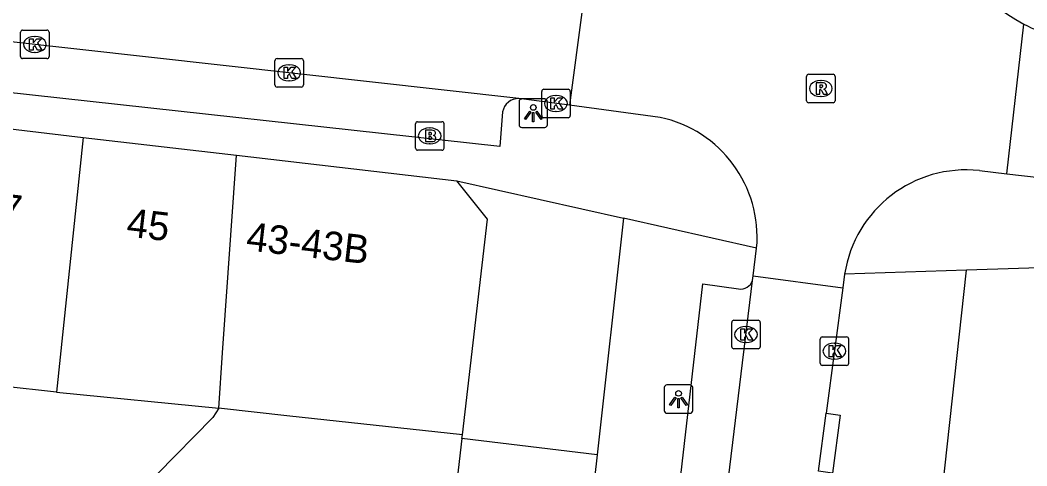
# Model space of a CAD drawing. Extents: x 161696 to 162377, y 380761 to 381673.
# Drawn here: x 162000.63 to 162035.97, y 381141.72 to 381157.36 of the extents above; entities that cross this region are included whole.
import ezdxf

# ---------------------------------------------------------------- set-up
doc = ezdxf.new("R2010")
doc.units = 0
for name, color, linetype in [('IMGEO_Brandkraan', 7, 'Continuous'), ('IMGEO_Kolk', 7, 'Continuous'), ('IMGEO_Lichtpunt', 7, 'Continuous'), ('IMGEO_Pand', 7, 'Continuous'), ('IMGEO_Pand_nummerreeks', 7, 'Continuous'), ('IMGEO_Rijbaan_lokaal_open', 7, 'Continuous'), ('IMGEO_Rioolput', 7, 'Continuous'), ('IMGEO_Voetpad_open', 7, 'Continuous')]:
    doc.layers.add(name, color=color, linetype=linetype)

msp = doc.modelspace()

# ---------------------------------------------------------------- linework, layer by layer
at = {"layer": 'IMGEO_Brandkraan'}
for p, q in [((162014.51, 381152.872), (162014.51, 381153.724)), ((162014.585, 381153.798), (162015.437, 381153.798)), ((162015.511, 381153.724), (162015.511, 381152.872)), ((162014.998, 381153.578), (162015.023, 381153.578)), ((162015.021, 381153.018), (162014.996, 381153.018)), ((162015.437, 381152.798), (162014.585, 381152.798))]:
    msp.add_line(p, q, dxfattribs=at)
for points in [[(162014.51, 381152.872), (162014.51, 381153.724)], [(162014.585, 381153.798), (162015.437, 381153.798)], [(162015.511, 381153.724), (162015.511, 381152.872)], [(162014.858, 381153.498), (162014.858, 381153.098), (162015.071, 381153.098)], [(162015.089, 381153.498), (162014.858, 381153.498)], [(162015.037, 381153.417), (162014.983, 381153.417), (162014.983, 381153.341)], [(162014.983, 381153.341), (162015.036, 381153.341)], [(162015.045, 381153.265), (162014.983, 381153.265), (162014.983, 381153.184)], [(162014.983, 381153.184), (162015.045, 381153.184)], [(162015.437, 381152.798), (162014.585, 381152.798)]]:
    msp.add_lwpolyline(points, dxfattribs=at)
for centre, radius, start, end in [((162014.587, 381153.722), 0.0765, 91.552, 178.448), ((162014.587, 381153.722), 0.0765, 91.552, 178.448), ((162015.435, 381153.722), 0.0765, 1.552, 88.448), ((162015.435, 381153.722), 0.0765, 1.552, 88.448), ((162015.038, 381153.379), 0.0379, 267.8285, 90.9355), ((162015.093, 381153.353), 0.145, 59.4692, 91.5367), ((162015.118, 381153.4), 0.0922, 285.5137, 58.1501), ((162015.123, 381153.208), 0.105, 301.3115, 78.989), ((162015.046, 381153.224), 0.0404, 269.8759, 90.5077), ((162015.077, 381153.349), 0.251, 268.6676, 293.5347), ((162014.587, 381152.874), 0.0765, 181.552, 268.448), ((162014.587, 381152.874), 0.0765, 181.552, 268.448), ((162015.435, 381152.874), 0.0765, 271.552, 358.448), ((162015.435, 381152.874), 0.0765, 271.552, 358.448)]:
    msp.add_arc(centre, radius, start, end, dxfattribs=at)
for centre, major_axis, ratio, start_param, end_param in [((162014.997, 381153.298), (-0.387, 0.002), 0.722429, 4.712389, 7.853982), ((162015.022, 381153.298), (-0.39, 0.002), 0.717154, 1.570796, 4.712389)]:
    msp.add_ellipse(centre, major_axis=major_axis, ratio=ratio, start_param=start_param, end_param=end_param, dxfattribs=at)
at = {"layer": 'IMGEO_Kolk'}
for p, q in [((162000.646, 381156.086), (162000.646, 381156.938)), ((162000.721, 381157.012), (162001.573, 381157.012)), ((162001.647, 381156.938), (162001.647, 381156.086)), ((162001.134, 381156.792), (162001.159, 381156.792)), ((162001.157, 381156.232), (162001.132, 381156.232)), ((162001.573, 381156.012), (162000.721, 381156.012)), ((162009.575, 381155.087), (162009.575, 381155.939)), ((162009.65, 381156.013), (162010.502, 381156.013)), ((162010.063, 381155.793), (162010.088, 381155.793)), ((162010.576, 381155.939), (162010.576, 381155.087)), ((162010.086, 381155.233), (162010.061, 381155.233)), ((162010.502, 381155.013), (162009.65, 381155.013)), ((162018.94, 381154.011), (162018.94, 381154.863)), ((162019.015, 381154.937), (162019.867, 381154.937)), ((162019.428, 381154.717), (162019.453, 381154.717)), ((162019.941, 381154.863), (162019.941, 381154.011)), ((162019.451, 381154.157), (162019.426, 381154.157)), ((162019.867, 381153.937), (162019.015, 381153.937)), ((162025.612, 381145.9), (162025.612, 381146.752)), ((162025.687, 381146.826), (162026.539, 381146.826)), ((162026.1, 381146.606), (162026.125, 381146.606)), ((162026.613, 381146.752), (162026.613, 381145.9)), ((162028.789, 381146.242), (162029.641, 381146.242)), ((162026.123, 381146.046), (162026.098, 381146.046)), ((162028.714, 381145.316), (162028.714, 381146.168)), ((162029.202, 381146.022), (162029.227, 381146.022)), ((162029.715, 381146.168), (162029.715, 381145.316)), ((162026.539, 381145.826), (162025.687, 381145.826)), ((162029.641, 381145.242), (162028.789, 381145.242)), ((162029.225, 381145.462), (162029.2, 381145.462))]:
    msp.add_line(p, q, dxfattribs=at)
for points in [[(162000.646, 381156.086), (162000.646, 381156.938)], [(162000.721, 381157.012), (162001.573, 381157.012)], [(162001.647, 381156.938), (162001.647, 381156.086)], [(162000.967, 381156.712), (162001.09, 381156.712), (162001.09, 381156.561), (162001.22, 381156.712), (162001.384, 381156.712), (162001.238, 381156.561), (162001.391, 381156.312), (162001.239, 381156.312), (162001.154, 381156.476), (162001.09, 381156.409), (162001.09, 381156.312), (162000.967, 381156.312), (162000.967, 381156.712)], [(162001.573, 381156.012), (162000.721, 381156.012)], [(162009.575, 381155.087), (162009.575, 381155.939)], [(162009.65, 381156.013), (162010.502, 381156.013)], [(162010.576, 381155.939), (162010.576, 381155.087)], [(162009.896, 381155.713), (162010.019, 381155.713), (162010.019, 381155.562), (162010.149, 381155.713), (162010.313, 381155.713), (162010.167, 381155.562), (162010.32, 381155.313), (162010.168, 381155.313), (162010.083, 381155.477), (162010.019, 381155.41), (162010.019, 381155.313), (162009.896, 381155.313), (162009.896, 381155.713)], [(162010.502, 381155.013), (162009.65, 381155.013)], [(162018.94, 381154.011), (162018.94, 381154.863)], [(162019.015, 381154.937), (162019.867, 381154.937)], [(162019.941, 381154.863), (162019.941, 381154.011)], [(162019.261, 381154.637), (162019.384, 381154.637), (162019.384, 381154.486), (162019.514, 381154.637), (162019.678, 381154.637), (162019.532, 381154.486), (162019.685, 381154.237), (162019.533, 381154.237), (162019.448, 381154.401), (162019.384, 381154.334), (162019.384, 381154.237), (162019.261, 381154.237), (162019.261, 381154.637)], [(162019.867, 381153.937), (162019.015, 381153.937)], [(162025.612, 381145.9), (162025.612, 381146.752)], [(162025.687, 381146.826), (162026.539, 381146.826)], [(162026.613, 381146.752), (162026.613, 381145.9)], [(162025.933, 381146.526), (162026.056, 381146.526), (162026.056, 381146.375), (162026.186, 381146.526), (162026.35, 381146.526), (162026.204, 381146.375), (162026.357, 381146.126), (162026.205, 381146.126), (162026.12, 381146.29), (162026.056, 381146.223), (162026.056, 381146.126), (162025.933, 381146.126), (162025.933, 381146.526)], [(162028.789, 381146.242), (162029.641, 381146.242)], [(162028.714, 381145.316), (162028.714, 381146.168)], [(162029.035, 381145.942), (162029.158, 381145.942), (162029.158, 381145.791), (162029.288, 381145.942), (162029.452, 381145.942), (162029.306, 381145.791), (162029.459, 381145.542), (162029.307, 381145.542), (162029.222, 381145.706), (162029.158, 381145.639), (162029.158, 381145.542), (162029.035, 381145.542), (162029.035, 381145.942)], [(162029.715, 381146.168), (162029.715, 381145.316)], [(162026.539, 381145.826), (162025.687, 381145.826)], [(162029.641, 381145.242), (162028.789, 381145.242)]]:
    msp.add_lwpolyline(points, dxfattribs=at)
for centre, start, end in [((162000.723, 381156.936), 91.552, 178.448), ((162000.723, 381156.936), 91.552, 178.448), ((162001.571, 381156.936), 1.552, 88.448), ((162001.571, 381156.936), 1.552, 88.448), ((162000.723, 381156.088), 181.552, 268.448), ((162000.723, 381156.088), 181.552, 268.448), ((162001.571, 381156.088), 271.552, 358.448), ((162001.571, 381156.088), 271.552, 358.448), ((162009.652, 381155.937), 91.552, 178.448), ((162009.652, 381155.937), 91.552, 178.448), ((162010.5, 381155.937), 1.552, 88.448), ((162010.5, 381155.937), 1.552, 88.448), ((162009.652, 381155.089), 181.552, 268.448), ((162009.652, 381155.089), 181.552, 268.448), ((162010.5, 381155.089), 271.552, 358.448), ((162010.5, 381155.089), 271.552, 358.448), ((162019.017, 381154.861), 91.552, 178.448), ((162019.017, 381154.861), 91.552, 178.448), ((162019.865, 381154.861), 1.552, 88.448), ((162019.865, 381154.861), 1.552, 88.448), ((162019.017, 381154.013), 181.552, 268.448), ((162019.017, 381154.013), 181.552, 268.448), ((162019.865, 381154.013), 271.552, 358.448), ((162019.865, 381154.013), 271.552, 358.448), ((162025.689, 381146.75), 91.552, 178.448), ((162025.689, 381146.75), 91.552, 178.448), ((162026.537, 381146.75), 1.552, 88.448), ((162026.537, 381146.75), 1.552, 88.448), ((162028.791, 381146.166), 91.552, 178.448), ((162028.791, 381146.166), 91.552, 178.448), ((162029.639, 381146.166), 1.552, 88.448), ((162029.639, 381146.166), 1.552, 88.448), ((162025.689, 381145.902), 181.552, 268.448), ((162025.689, 381145.902), 181.552, 268.448), ((162026.537, 381145.902), 271.552, 358.448), ((162026.537, 381145.902), 271.552, 358.448), ((162028.791, 381145.318), 181.552, 268.448), ((162028.791, 381145.318), 181.552, 268.448), ((162029.639, 381145.318), 271.552, 358.448), ((162029.639, 381145.318), 271.552, 358.448)]:
    msp.add_arc(centre, 0.0765, start, end, dxfattribs=at)
for centre, major_axis, ratio, start_param, end_param in [((162001.133, 381156.512), (-0.387, 0.002), 0.722429, 4.712389, 7.853982), ((162001.158, 381156.512), (-0.39, 0.002), 0.717154, 1.570796, 4.712389), ((162010.062, 381155.513), (-0.387, 0.002), 0.722429, 4.712389, 7.853982), ((162010.087, 381155.513), (-0.39, 0.002), 0.717154, 1.570796, 4.712389), ((162019.427, 381154.437), (-0.387, 0.002), 0.722429, 4.712389, 7.853982), ((162019.452, 381154.437), (-0.39, 0.002), 0.717154, 1.570796, 4.712389), ((162026.099, 381146.326), (-0.387, 0.002), 0.722429, 4.712389, 7.853982), ((162026.124, 381146.326), (-0.39, 0.002), 0.717154, 1.570796, 4.712389), ((162029.201, 381145.742), (-0.387, 0.002), 0.722429, 4.712389, 7.853982), ((162029.226, 381145.742), (-0.39, 0.002), 0.717154, 1.570796, 4.712389)]:
    msp.add_ellipse(centre, major_axis=major_axis, ratio=ratio, start_param=start_param, end_param=end_param, dxfattribs=at)
at = {"layer": 'IMGEO_Lichtpunt'}
for p, q in [((162018.146, 381154.5), (162018.146, 381153.693)), ((162018.146, 381154.5), (162018.146, 381153.693)), ((162019.048, 381154.595), (162018.24, 381154.595)), ((162019.048, 381154.595), (162018.24, 381154.595)), ((162019.142, 381153.693), (162019.142, 381154.5)), ((162019.142, 381153.693), (162019.142, 381154.5)), ((162018.24, 381153.599), (162019.048, 381153.599)), ((162018.24, 381153.599), (162019.048, 381153.599)), ((162023.244, 381144.463), (162023.244, 381143.656)), ((162023.244, 381144.463), (162023.244, 381143.656)), ((162024.146, 381144.558), (162023.338, 381144.558)), ((162024.146, 381144.558), (162023.338, 381144.558)), ((162024.24, 381143.656), (162024.24, 381144.463)), ((162024.24, 381143.656), (162024.24, 381144.463)), ((162023.338, 381143.562), (162024.146, 381143.562)), ((162023.338, 381143.562), (162024.146, 381143.562))]:
    msp.add_line(p, q, dxfattribs=at)
for points in [[(162018.52, 381154.164), (162018.559, 381154.136), (162018.371, 381153.874), (162018.333, 381153.901), (162018.52, 381154.164)], [(162018.622, 381154.116), (162018.669, 381154.116), (162018.669, 381153.794), (162018.622, 381153.794), (162018.622, 381154.116)], [(162018.732, 381154.136), (162018.77, 381154.163), (162018.957, 381153.901), (162018.918, 381153.873), (162018.732, 381154.136)], [(162023.618, 381144.127), (162023.657, 381144.099), (162023.469, 381143.837), (162023.431, 381143.864), (162023.618, 381144.127)], [(162023.83, 381144.099), (162023.868, 381144.126), (162024.055, 381143.864), (162024.016, 381143.836), (162023.83, 381144.099)], [(162023.72, 381144.079), (162023.767, 381144.079), (162023.767, 381143.757), (162023.72, 381143.757), (162023.72, 381144.079)]]:
    msp.add_lwpolyline(points, dxfattribs=at)
for centre in [(162018.645, 381154.298), (162023.743, 381144.261)]:
    msp.add_circle(centre, 0.0994, dxfattribs=at)
for centre, start, end in [((162018.24, 381154.5), 90, 180), ((162018.24, 381154.5), 90, 180), ((162019.048, 381154.5), 0, 90), ((162019.048, 381154.5), 0, 90), ((162018.24, 381153.693), 180, 270), ((162018.24, 381153.693), 180, 270), ((162019.048, 381153.693), 270, 0), ((162019.048, 381153.693), 270, 360), ((162023.338, 381144.463), 90, 180), ((162023.338, 381144.463), 90, 180), ((162024.146, 381144.463), 0, 90), ((162024.146, 381144.463), 0, 90), ((162023.338, 381143.656), 180, 270), ((162023.338, 381143.656), 180, 270), ((162024.146, 381143.656), 270, 0), ((162024.146, 381143.656), 270, 360)]:
    msp.add_arc(centre, 0.0946, start, end, dxfattribs=at)
at = {"layer": 'IMGEO_Pand'}
for points in [[(161997.875, 381153.822), (161999.999, 381153.577), (162002.848, 381153.247)], [(162002.848, 381153.247), (162001.908, 381144.298)], [(162002.848, 381153.247), (162008.224, 381152.624)], [(162007.603, 381143.738), (162007.739, 381145.683), (162008.224, 381152.624)], [(162008.224, 381152.624), (162015.967, 381151.726)], [(162016.155, 381142.8), (162017.034, 381150.379), (162015.967, 381151.726)], [(162001.908, 381144.298), (162000, 381144.519), (161996.841, 381144.883)], [(162001.908, 381144.298), (162007.603, 381143.738)], [(162007.603, 381143.738), (162007.398, 381143.413), (162005.443, 381141.419), (162005.189, 381141.16), (162004.938, 381140.904), (162004.737, 381139.167)], [(162016.155, 381142.8), (162009.994, 381143.476), (162007.705, 381143.727), (162007.603, 381143.738)], [(162016.141, 381142.676), (162015.438, 381136.612)], [(162016.141, 381142.676), (162016.155, 381142.8)]]:
    msp.add_lwpolyline(points, dxfattribs=at)
at = {"layer": 'IMGEO_Rijbaan_lokaal_open'}
for points in [[(162020.371, 381157.806), (162019.912, 381154.375)], [(162018.142, 381154.612), (162000, 381156.642), (161996.097, 381157.078), (161993.884, 381157.342)], [(162035.272, 381151.971), (162035.868, 381157.223)], [(162019.912, 381154.375), (162018.142, 381154.612)], [(162023.097, 381153.949), (162019.912, 381154.375)], [(162034.305, 381152.081), (162035.272, 381151.971)], [(162035.272, 381151.971), (162046.318, 381150.716), (162059.956, 381149.132), (162076.958, 381147.175), (162083.226, 381146.452), (162088.674, 381145.807)], [(162026.366, 381148.384), (162026.485, 381149.36)], [(162026.345, 381148.219), (162026.366, 381148.384)], [(162026.366, 381148.384), (162029.51, 381147.963)], [(162029.575, 381148.446), (162029.51, 381147.963)], [(162019.742, 381091.725), (162021.634, 381108.154), (162023.561, 381124.838), (162025.096, 381138.002), (162026.345, 381148.219)], [(162029.51, 381147.963), (162028.922, 381143.563)], [(162028.651, 381141.53), (162028.922, 381143.563)]]:
    msp.add_lwpolyline(points, dxfattribs=at)
for centre, radius, start, end in [((162038.683, 381162.578), 6.05, 192.7782, 242.2693), ((162038.683, 381162.572), 6.045, 242.2472, 263.2955), ((162022.203, 381149.744), 4.299, 354.8755, 78.0004), ((162033.841, 381147.789), 4.317, 83.8334, 171.251)]:
    msp.add_arc(centre, radius, start, end, dxfattribs=at)
at = {"layer": 'IMGEO_Rioolput'}
for p, q in [((162028.314, 381155.462), (162029.166, 381155.462)), ((162028.239, 381154.536), (162028.239, 381155.388)), ((162028.727, 381155.242), (162028.752, 381155.242)), ((162029.24, 381155.388), (162029.24, 381154.536)), ((162029.166, 381154.462), (162028.314, 381154.462)), ((162028.75, 381154.682), (162028.725, 381154.682))]:
    msp.add_line(p, q, dxfattribs=at)
for points in [[(162028.314, 381155.462), (162029.166, 381155.462)], [(162028.239, 381154.536), (162028.239, 381155.388)], [(162028.828, 381155.16), (162028.576, 381155.162), (162028.576, 381154.762)], [(162028.754, 381155.081), (162028.7, 381155.081), (162028.7, 381155)], [(162029.24, 381155.388), (162029.24, 381154.536)], [(162028.576, 381154.762), (162028.7, 381154.762), (162028.7, 381154.924), (162028.711, 381154.924)], [(162028.7, 381155), (162028.752, 381155)], [(162028.758, 381154.895), (162028.829, 381154.762), (162028.969, 381154.762), (162028.904, 381154.888)], [(162029.166, 381154.462), (162028.314, 381154.462)]]:
    msp.add_lwpolyline(points, dxfattribs=at)
for centre, radius, start, end in [((162028.316, 381155.386), 0.0765, 91.552, 178.448), ((162028.316, 381155.386), 0.0765, 91.552, 178.448), ((162029.164, 381155.386), 0.0765, 1.552, 88.448), ((162029.164, 381155.386), 0.0765, 1.552, 88.448), ((162028.76, 381154.985), 0.0964, 77.0061, 93.1865), ((162028.774, 381155.042), 0.0378, 276.6634, 79.6772), ((162028.827, 381155.05), 0.109, 350.3612, 89.416), ((162028.71, 381154.871), 0.0533, 26.0293, 88.6989), ((162028.736, 381155.189), 0.19, 274.7715, 282.9687), ((162028.825, 381155.05), 0.112, 277.5842, 350.9817), ((162028.809, 381154.835), 0.108, 29.5134, 73.7905), ((162028.316, 381154.538), 0.0765, 181.552, 268.448), ((162028.316, 381154.538), 0.0765, 181.552, 268.448), ((162029.164, 381154.538), 0.0765, 271.552, 358.448), ((162029.164, 381154.538), 0.0765, 271.552, 358.448)]:
    msp.add_arc(centre, radius, start, end, dxfattribs=at)
for centre, major_axis, ratio, start_param, end_param in [((162028.726, 381154.962), (-0.387, 0.002), 0.722429, 4.712389, 7.853982), ((162028.751, 381154.962), (-0.39, 0.002), 0.717154, 1.570796, 4.712389)]:
    msp.add_ellipse(centre, major_axis=major_axis, ratio=ratio, start_param=start_param, end_param=end_param, dxfattribs=at)
at = {"layer": 'IMGEO_Voetpad_open'}
for points in [[(162017.568, 381154.144), (162017.471, 381152.925), (162000, 381154.847), (161994.156, 381155.567), (161994.285, 381156.709)], [(162015.967, 381151.726), (162021.813, 381150.411)], [(162021.813, 381150.411), (162020.89, 381142.109)], [(162026.485, 381149.36), (162021.813, 381150.411)], [(162040.047, 381148.788), (162033.856, 381148.586)], [(162027.003, 381088.756), (162032.093, 381132.546), (162033.856, 381148.586)], [(162033.856, 381148.586), (162029.575, 381148.446)], [(162019.694, 381091.309), (162019.352, 381091.773), (162018.133, 381091.846), (162024.595, 381148.112), (162025.853, 381147.926)], [(162028.922, 381143.563), (162029.417, 381143.497), (162029.146, 381141.464), (162028.651, 381141.53)], [(162020.89, 381142.109), (162016.141, 381142.676)], [(162020.89, 381142.109), (162015.25, 381092.109)]]:
    msp.add_lwpolyline(points, dxfattribs=at)
for centre, radius, start, end in [((162018.135, 381154.034), 0.578, 89.318, 169.0649), ((162025.908, 381148.393), 0.47, 263.2272, 338.3228)]:
    msp.add_arc(centre, radius, start, end, dxfattribs=at)

# ---------------------------------------------------------------- texts
at = {"layer": 'IMGEO_Pand_nummerreeks'}
for s, rotation, p in [('47', 353.4045, (161999.164, 381150.373)), ('45', 353.3881, (162004.337, 381149.773)), ('43-43B', 353.4568, (162008.539, 381149.287))]:
    msp.add_text(s, height=1, rotation=rotation, dxfattribs=at).set_placement(p)

doc.saveas('drawing.dxf')
